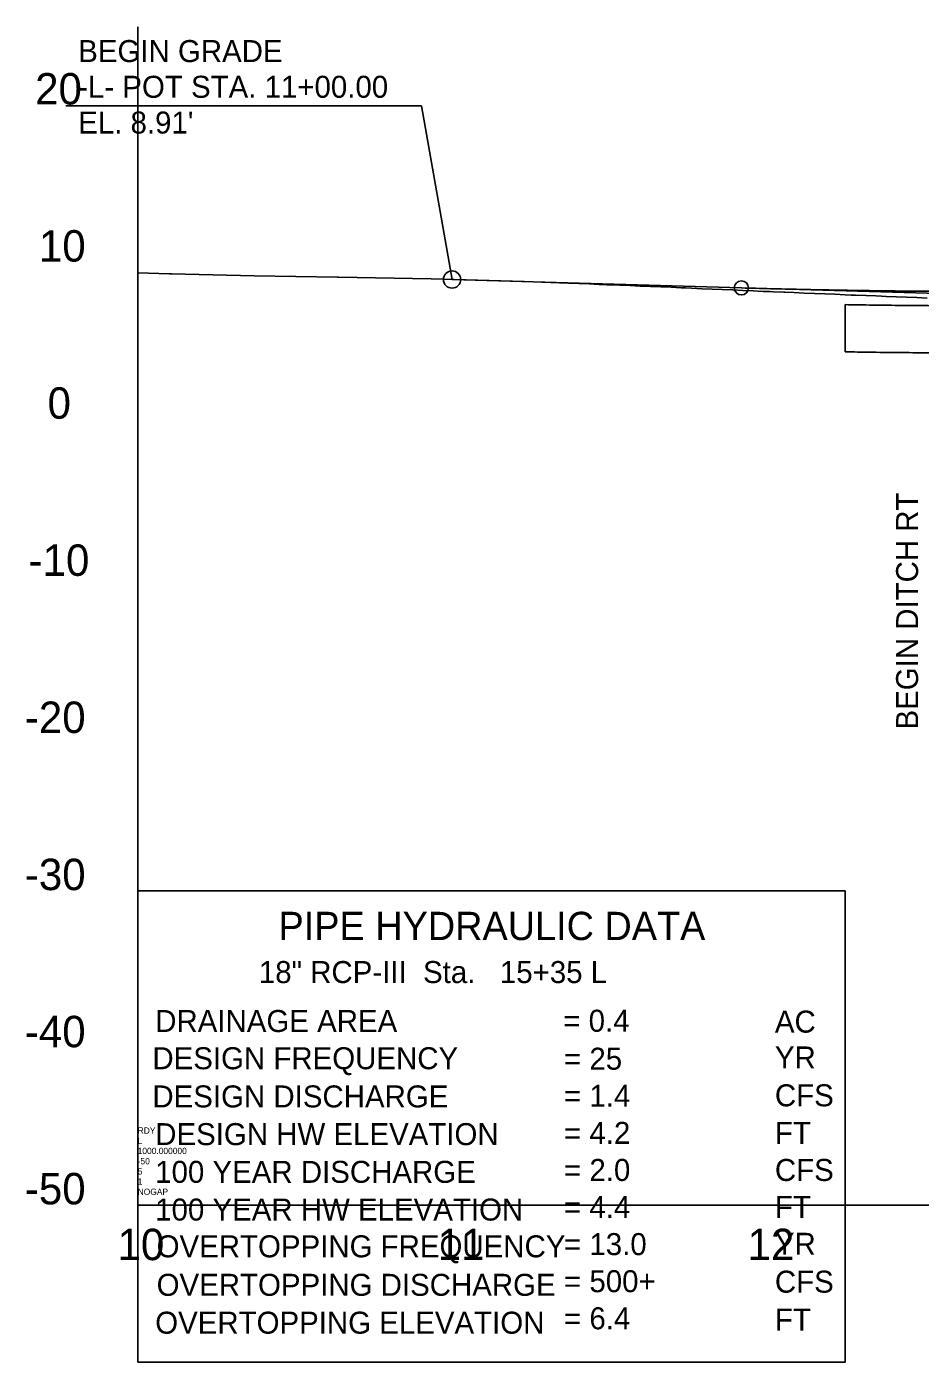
# Model space of a CAD drawing. Extents: x 1626634 to 1638383, y 876896 to 886347.
# Drawn here: x 1632678.6 to 1632962.8, y 883997.6 to 884422.6 of the extents above; entities that cross this region are included whole.
import ezdxf

# ---------------------------------------------------------------- set-up
doc = ezdxf.new("R2010")
doc.units = 0
for name, color, linetype in [('Exist Profile Cell', 7, 'Continuous'), ('Exist Vertical Profile Ground Line', 7, 'Continuous'), ('Exist Vertical Profile Horizontal Axis Label Major', 7, 'Continuous'), ('Exist Vertical Profile Vertical Axis Label', 7, 'Continuous'), ('Old_Level_1', 7, 'Continuous'), ('Prop Shade Light', 7, 'Continuous'), ('Prop Vertical Profile Curve Label', 7, 'Continuous'), ('Prop Vertical Profile Grade', 7, 'Continuous'), ('Prop VPI Label', 7, 'Continuous'), ('Scratch_Level_3', 7, 'Continuous')]:
    doc.layers.add(name, color=color, linetype=linetype)

msp = doc.modelspace()

# ---------------------------------------------------------------- linework, layer by layer
at = {"layer": 'Exist Profile Cell'}
for q in [(1632713.86, 884422.61), (1634948.96, 884047.61), (1632713.86, 884047.61)]:
    msp.add_line((1632713.86, 884047.61), q, dxfattribs=at)
at = {"layer": 'Exist Vertical Profile Ground Line'}
msp.add_lwpolyline([(1632713.86, 884344.29), (1632723.99, 884343.97), (1632724.58, 884343.96), (1632750.88, 884343.38), (1632777.4, 884342.93), (1632777.74, 884342.93), (1632807.24, 884342.34), (1632836.74, 884341.55), (1632850.92, 884341), (1632854.18, 884340.87), (1632857.44, 884340.75), (1632860.69, 884340.62), (1632863.06, 884340.52), (1632863.95, 884340.49), (1632867.21, 884340.35), (1632870.47, 884340.22), (1632873.73, 884340.08), (1632876.99, 884339.95), (1632880.24, 884339.81), (1632883.5, 884339.68), (1632886.76, 884339.54), (1632888.14, 884339.48), (1632890.02, 884339.38), (1632893.28, 884339.24), (1632896.54, 884339.1), (1632899.79, 884338.97), (1632903.05, 884338.83), (1632906.31, 884338.69), (1632909.57, 884338.54), (1632912.83, 884338.4), (1632914.91, 884338.31), (1632916.09, 884338.27), (1632919.34, 884338.14), (1632919.75, 884338.13), (1632922.6, 884338.01), (1632925.86, 884337.87), (1632929.12, 884337.73), (1632932.38, 884337.59), (1632935.64, 884337.45), (1632938.89, 884337.31), (1632940.83, 884337.22), (1632942.15, 884337.17), (1632945.41, 884337.05), (1632948.67, 884336.92), (1632950.43, 884336.85), (1632951.93, 884336.79), (1632955.19, 884336.67), (1632958.44, 884336.54), (1632961.7, 884336.41), (1632964.96, 884336.28)], dxfattribs=at)
at = {"layer": 'Prop Shade Light'}
msp.add_lwpolyline([(1632713.86, 883997.61), (1632938.86, 883997.61), (1632938.86, 884147.61), (1632713.86, 884147.61)], close=True, dxfattribs=at)
at = {"layer": 'Prop Vertical Profile Curve Label'}
msp.add_circle((1632905.86, 884339.49), 2.25, dxfattribs=at)
at = {"layer": 'Prop Vertical Profile Grade'}
msp.add_line((1632813.86, 884342.16), (1632905.86, 884339.49), dxfattribs=at)
msp.add_spline([(1632905.86, 884339.49), (1632915.18, 884339.24), (1632924.5, 884339.02), (1632933.82, 884338.83), (1632943.14, 884338.67), (1632952.46, 884338.54), (1632961.78, 884338.45), (1632971.1, 884338.39), (1632980.42, 884338.36), (1632989.74, 884338.36), (1632999.06, 884338.39), (1633008.38, 884338.46), (1633017.7, 884338.56), (1633027.02, 884338.68), (1633036.34, 884338.85), (1633045.66, 884339.04), (1633054.98, 884339.26), (1633064.3, 884339.52), (1633073.62, 884339.81), (1633082.94, 884340.13), (1633092.26, 884340.48), (1633101.58, 884340.87), (1633110.9, 884341.28), (1633120.22, 884341.73), (1633129.54, 884342.21), (1633138.86, 884342.73), (1633148.18, 884343.27), (1633157.5, 884343.85), (1633166.82, 884344.45), (1633176.14, 884345.09), (1633185.46, 884345.77), (1633194.78, 884346.47), (1633204.1, 884347.21), (1633213.42, 884347.97), (1633222.74, 884348.77), (1633232.06, 884349.61), (1633241.38, 884350.47), (1633250.7, 884351.36), (1633260.02, 884352.29), (1633269.34, 884353.25), (1633278.66, 884354.24), (1633287.98, 884355.27), (1633297.3, 884356.32), (1633306.62, 884357.41), (1633315.94, 884358.53), (1633325.26, 884359.68), (1633334.58, 884360.86), (1633343.9, 884362.08), (1633353.22, 884363.32), (1633362.54, 884364.6), (1633371.86, 884365.91)], degree=3, dxfattribs=at)
at = {"layer": 'Prop VPI Label'}
for p, q in [((1632804.14, 884397.47), (1632691.03, 884397.47)), ((1632813.86, 884342.14), (1632804.14, 884397.47)), ((1632905.86, 884339.49), (1633136.11, 884332.83))]:
    msp.add_line(p, q, dxfattribs=at)
msp.add_circle((1632813.86, 884342.16), 2.75, dxfattribs=at)
msp.add_circle((1632813.86, 884342.16), 2.75, dxfattribs=at)
msp.add_circle((1632813.86, 884342.16), 2.75, dxfattribs=at)
at = {"layer": 'Scratch_Level_3'}
msp.add_line((1632938.86, 884319.15), (1632938.86, 884334.16), dxfattribs=at)
for points in [[(1632938.86, 884334.16), (1632943.07, 884334.09), (1632952.41, 884333.96), (1632961.74, 884333.87), (1632971.08, 884333.8), (1632980.42, 884333.77), (1632989.75, 884333.78), (1632999.09, 884333.81), (1633008.42, 884333.87), (1633017.76, 884333.97), (1633027.09, 884334.1), (1633036.43, 884334.26), (1633045.77, 884334.46), (1633055.1, 884334.68), (1633064.44, 884334.94), (1633073.77, 884335.23), (1633083.11, 884335.55), (1633088.86, 884335.76)], [(1633088.86, 884320.75), (1633083.65, 884320.56), (1633074.26, 884320.24), (1633064.88, 884319.95), (1633055.49, 884319.69), (1633046.1, 884319.46), (1633036.72, 884319.27), (1633027.33, 884319.1), (1633017.94, 884318.97), (1633008.55, 884318.88), (1632999.17, 884318.81), (1632989.78, 884318.78), (1632980.39, 884318.77), (1632971.01, 884318.8), (1632961.62, 884318.87), (1632952.23, 884318.96), (1632942.84, 884319.09), (1632938.86, 884319.15)]]:
    msp.add_spline(points, degree=3, dxfattribs=at)

# ---------------------------------------------------------------- texts
at = {"layer": 'Exist Profile Cell'}
for s, p in [('RDY', (1632713.86, 884070.36)), ('L', (1632713.86, 884067.11)), ('1000.000000', (1632713.86, 884063.86)), ('-50', (1632713.86, 884060.61)), ('5', (1632713.86, 884057.36)), ('1', (1632713.86, 884054.11)), ('NOGAP', (1632713.86, 884050.86))]:
    msp.add_text(s, height=2, dxfattribs=at).set_placement(p)
at = {"layer": 'Exist Vertical Profile Horizontal Axis Label Major'}
for s, p in [('10', (1632707.45, 884030.11)), ('11', (1632809.29, 884030.11)), ('12', (1632907.83, 884030.11))]:
    msp.add_text(s, height=10, dxfattribs=at).set_placement(p)
at = {"layer": 'Exist Vertical Profile Vertical Axis Label'}
for s, p in [('20', (1632681.25, 884397.86)), ('10', (1632682.45, 884347.86)), ('0', (1632685.2, 884297.86)), ('-10', (1632679.17, 884247.86)), ('-20', (1632677.98, 884197.86)), ('-30', (1632677.98, 884147.86)), ('-40', (1632677.98, 884097.86)), ('-50', (1632677.98, 884047.86))]:
    msp.add_text(s, height=10, dxfattribs=at).set_placement(p)
at = {"layer": 'Old_Level_1'}
msp.add_text('BEGIN DITCH RT', height=7, rotation=90, dxfattribs=at).set_placement((1632962.08, 884198.97))
at = {"layer": 'Prop Shade Light'}
for s, height, p in [('PIPE HYDRAULIC DATA', 8.9997, (1632758.66, 884131.96)), ('18" RCP-III  Sta.   15+35 L ', 6.9996, (1632752.4, 884118.28)), ('DRAINAGE AREA', 6.9999, (1632719.44, 884102.71)), ('= 0.4    ', 7, (1632849.23, 884102.79)), ('AC', 7, (1632916.53, 884102.51)), ('DESIGN FREQUENCY', 6.9999, (1632718.54, 884090.86)), ('= 25 ', 7, (1632849.47, 884090.71)), ('YR', 7, (1632916.53, 884091.11)), ('DESIGN DISCHARGE', 6.9999, (1632718.54, 884078.71)), ('= 1.4     ', 7, (1632849.47, 884078.91)), ('CFS', 7, (1632916.53, 884079.06)), ('DESIGN HW ELEVATION', 6.9999, (1632719.44, 884066.71)), ('= 4.2     ', 7, (1632849.47, 884067.11)), ('FT', 7, (1632916.53, 884067.11)), ('100 YEAR DISCHARGE', 6.9999, (1632719.44, 884054.71)), ('= 2.0     ', 7, (1632849.47, 884055.31)), ('CFS', 7, (1632916.53, 884055.31)), ('100 YEAR HW ELEVATION', 6.9999, (1632719.44, 884042.71)), ('= 4.4     ', 7, (1632849.47, 884043.51)), ('FT', 7, (1632916.53, 884043.51)), ('= 13.0', 7, (1632849.47, 884031.71)), ('YR', 7, (1632916.53, 884031.81)), ('OVERTOPPING FREQUENCY', 6.9999, (1632719.89, 884031.01)), ('OVERTOPPING DISCHARGE', 6.9999, (1632719.89, 884018.76)), ('= 500+    ', 7, (1632849.47, 884019.91)), ('CFS', 7, (1632916.53, 884019.76)), ('OVERTOPPING ELEVATION', 6.9999, (1632719.44, 884006.71)), ('= 6.4     ', 7, (1632849.47, 884008.11)), ('FT', 7, (1632916.53, 884007.71))]:
    msp.add_text(s, height=height, dxfattribs=at).set_placement(p)
at = {"layer": 'Prop VPI Label'}
for s, p in [('BEGIN GRADE', (1632694.94, 884411.36)), ('-L- POT STA. 11+00.00', (1632694.94, 884399.99)), ("EL. 8.91'", (1632694.94, 884388.61))]:
    msp.add_text(s, height=7, dxfattribs=at).set_placement(p)

doc.saveas('drawing.dxf')
